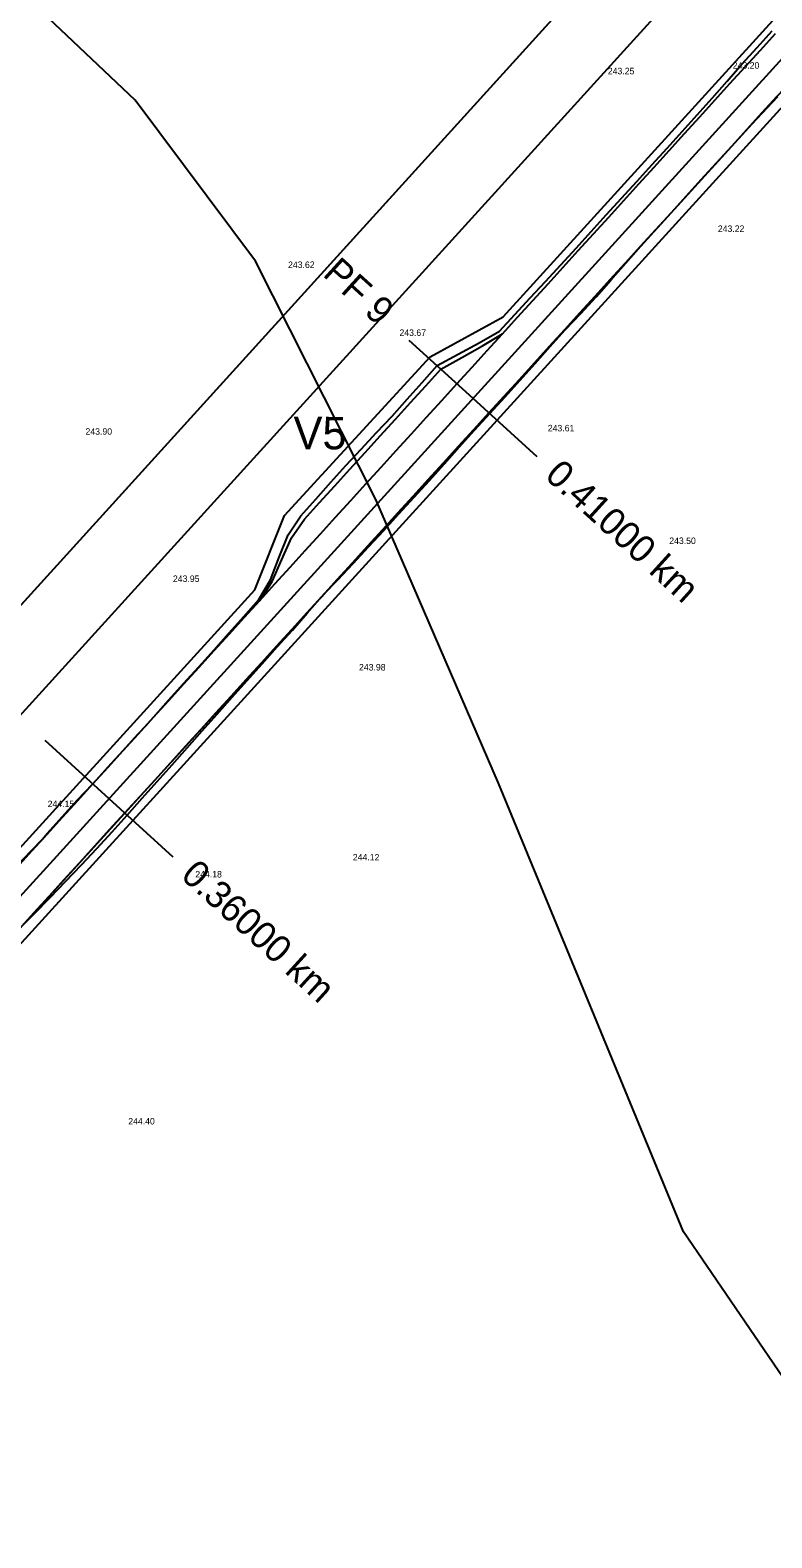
# Model space of a CAD drawing. Extents: x -555887 to -552101, y -1100251 to -1096546.
# Drawn here: x -554649.9 to -554581.4, y -1097394.3 to -1097254.9 of the extents above; entities that cross this region are included whole.
import ezdxf

# ---------------------------------------------------------------- set-up
doc = ezdxf.new("R2010")
doc.units = 0
for name, color, linetype in [('IP_návrh', 7, 'Continuous'), ('PARCELY_cesty', 7, 'Continuous'), ('POLYGONY_POPIS_CESTY', 7, 'Continuous'), ('POLYGONY_SITUACE_PF', 7, 'Continuous'), ('POLYGONY_SITUACE_PF_POPISY', 7, 'Continuous'), ('POLYGONY_SITUACE_PO', 7, 'Continuous'), ('vrstevnice', 7, 'Continuous'), ('Výškopis', 7, 'Continuous'), ('zájem', 7, 'Continuous')]:
    doc.layers.add(name, color=color, linetype=linetype)

msp = doc.modelspace()

# ---------------------------------------------------------------- linework, layer by layer
at = {"layer": 'IP_návrh'}
msp.add_line((-554875.9, -1097565.92), (-554275.99, -1096905.69), dxfattribs=at)
at = {"layer": 'PARCELY_cesty'}
for points in [[(-554879.07, -1097590.15), (-554550.67, -1097229.32), (-554531.76, -1097208.54), (-554275.81, -1096927.3), (-554273.04, -1096923.94), (-554268.63, -1096916.51), (-554265.12, -1096907.97), (-554264.18, -1096901.52)], [(-554875.85, -1097577.71), (-554629.16, -1097306.65), (-554626.42, -1097299.8), (-554612.94, -1097285.13), (-554606.19, -1097281.41), (-554359.61, -1097010.48), (-554356.78, -1097004.21), (-554343, -1096989.28), (-554337.66, -1096986.36), (-554280.34, -1096923.38), (-554277.96, -1096920.48), (-554274.11, -1096913.98), (-554271.59, -1096906.68), (-554270.35, -1096901.41)]]:
    msp.add_lwpolyline(points, dxfattribs=at)
at = {"layer": 'POLYGONY_SITUACE_PF'}
for p, q in [((-554614.91, -1097283.57), (-554609, -1097288.95)), ((-554609, -1097288.95), (-554603.08, -1097294.34)), ((-554648.57, -1097320.55), (-554642.65, -1097325.93)), ((-554642.65, -1097325.93), (-554636.74, -1097331.32))]:
    msp.add_line(p, q, dxfattribs=at)
at = {"layer": 'POLYGONY_SITUACE_PO'}
for p, q in [((-554884.96, -1097592.18), (-554278.08, -1096925.34)), ((-554878.71, -1097588.28), (-554338.29, -1096994.47)), ((-554582.73, -1097256.52), (-554581.33, -1097254.98)), ((-554584.13, -1097258.06), (-554582.73, -1097256.52)), ((-554582.43, -1097256.79), (-554581.03, -1097255.25)), ((-554582.43, -1097256.79), (-554581.03, -1097255.25)), ((-554583.83, -1097258.33), (-554582.43, -1097256.79)), ((-554583.83, -1097258.33), (-554582.43, -1097256.79)), ((-554585.5, -1097259.63), (-554584.13, -1097258.06)), ((-554585.24, -1097259.87), (-554583.83, -1097258.33)), ((-554585.24, -1097259.87), (-554583.83, -1097258.33)), ((-554586.88, -1097261.2), (-554585.5, -1097259.63)), ((-554586.64, -1097261.41), (-554585.24, -1097259.87)), ((-554586.64, -1097261.41), (-554585.24, -1097259.87)), ((-554588.27, -1097262.75), (-554586.88, -1097261.2)), ((-554588.04, -1097262.95), (-554586.64, -1097261.41)), ((-554588.04, -1097262.95), (-554586.64, -1097261.41)), ((-554582.28, -1097262.56), (-554580.88, -1097261.02)), ((-554582.25, -1097262.59), (-554580.82, -1097261.07)), ((-554589.65, -1097264.3), (-554588.27, -1097262.75)), ((-554589.44, -1097264.49), (-554588.04, -1097262.95)), ((-554589.44, -1097264.49), (-554588.04, -1097262.95)), ((-554583.68, -1097264.11), (-554582.28, -1097262.56)), ((-554583.67, -1097264.12), (-554582.25, -1097262.59)), ((-554591.05, -1097265.85), (-554589.65, -1097264.3)), ((-554590.85, -1097266.04), (-554589.44, -1097264.49)), ((-554590.85, -1097266.04), (-554589.44, -1097264.49)), ((-554585.08, -1097265.65), (-554583.68, -1097264.11)), ((-554585.07, -1097265.66), (-554583.67, -1097264.12)), ((-554592.45, -1097267.39), (-554591.05, -1097265.85)), ((-554592.25, -1097267.58), (-554590.85, -1097266.04)), ((-554592.25, -1097267.58), (-554590.85, -1097266.04)), ((-554586.48, -1097267.19), (-554585.08, -1097265.65)), ((-554586.48, -1097267.19), (-554585.07, -1097265.66)), ((-554593.86, -1097268.92), (-554592.45, -1097267.39)), ((-554593.65, -1097269.12), (-554592.25, -1097267.58)), ((-554593.65, -1097269.12), (-554592.25, -1097267.58)), ((-554587.89, -1097268.73), (-554586.48, -1097267.19)), ((-554587.88, -1097268.73), (-554586.48, -1097267.19)), ((-554595.26, -1097270.46), (-554593.86, -1097268.92)), ((-554595.05, -1097270.66), (-554593.65, -1097269.12)), ((-554595.05, -1097270.66), (-554593.65, -1097269.12)), ((-554589.29, -1097270.27), (-554587.89, -1097268.73)), ((-554589.29, -1097270.27), (-554587.88, -1097268.73)), ((-554596.67, -1097272.01), (-554595.26, -1097270.46)), ((-554590.69, -1097271.81), (-554589.29, -1097270.27)), ((-554590.69, -1097271.81), (-554589.29, -1097270.27)), ((-554596.45, -1097272.2), (-554595.05, -1097270.66)), ((-554596.45, -1097272.2), (-554595.05, -1097270.66)), ((-554592.09, -1097273.35), (-554590.69, -1097271.81)), ((-554592.08, -1097273.36), (-554590.69, -1097271.81)), ((-554598.07, -1097273.55), (-554596.67, -1097272.01)), ((-554597.86, -1097273.74), (-554596.45, -1097272.2)), ((-554597.86, -1097273.74), (-554596.45, -1097272.2)), ((-554599.47, -1097275.09), (-554598.07, -1097273.55)), ((-554599.26, -1097275.28), (-554597.86, -1097273.74)), ((-554599.26, -1097275.28), (-554597.86, -1097273.74)), ((-554593.5, -1097274.89), (-554592.09, -1097273.35)), ((-554593.48, -1097274.9), (-554592.08, -1097273.36)), ((-554600.87, -1097276.63), (-554599.47, -1097275.09)), ((-554600.66, -1097276.82), (-554599.26, -1097275.28)), ((-554600.66, -1097276.82), (-554599.26, -1097275.28)), ((-554594.9, -1097276.43), (-554593.5, -1097274.89)), ((-554594.87, -1097276.45), (-554593.48, -1097274.9)), ((-554602.3, -1097278.15), (-554600.87, -1097276.63)), ((-554602.06, -1097278.36), (-554600.66, -1097276.82)), ((-554602.06, -1097278.36), (-554600.66, -1097276.82)), ((-554596.3, -1097277.97), (-554594.9, -1097276.43)), ((-554596.25, -1097278.02), (-554594.87, -1097276.45)), ((-554603.71, -1097279.68), (-554602.3, -1097278.15)), ((-554603.47, -1097279.9), (-554602.06, -1097278.36)), ((-554603.47, -1097279.9), (-554602.06, -1097278.36)), ((-554597.7, -1097279.51), (-554596.3, -1097277.97)), ((-554597.62, -1097279.59), (-554596.25, -1097278.02)), ((-554605.12, -1097281.21), (-554603.71, -1097279.68)), ((-554604.87, -1097281.44), (-554603.47, -1097279.9)), ((-554604.87, -1097281.44), (-554603.47, -1097279.9)), ((-554599.11, -1097281.05), (-554597.7, -1097279.51)), ((-554599.03, -1097281.12), (-554597.62, -1097279.59)), ((-554606.54, -1097282.74), (-554605.12, -1097281.21)), ((-554606.27, -1097282.98), (-554604.87, -1097281.44)), ((-554606.27, -1097282.98), (-554604.87, -1097281.44)), ((-554600.51, -1097282.59), (-554599.11, -1097281.05)), ((-554600.46, -1097282.64), (-554599.03, -1097281.12)), ((-554608.42, -1097283.84), (-554606.54, -1097282.74)), ((-554608.12, -1097284.11), (-554606.27, -1097282.98)), ((-554607.67, -1097284.52), (-554606.27, -1097282.98)), ((-554601.91, -1097284.14), (-554600.51, -1097282.59)), ((-554601.86, -1097284.18), (-554600.46, -1097282.64)), ((-554610.37, -1097284.88), (-554608.42, -1097283.84)), ((-554610.04, -1097285.19), (-554608.12, -1097284.11)), ((-554603.31, -1097285.68), (-554601.91, -1097284.14)), ((-554603.24, -1097285.74), (-554601.86, -1097284.18)), ((-554612.31, -1097285.93), (-554610.37, -1097284.88)), ((-554611.96, -1097286.26), (-554610.04, -1097285.19)), ((-554609.07, -1097286.07), (-554607.67, -1097284.52)), ((-554604.71, -1097287.22), (-554603.31, -1097285.68)), ((-554604.63, -1097287.29), (-554603.24, -1097285.74)), ((-554613.7, -1097287.49), (-554612.31, -1097285.93)), ((-554613.36, -1097287.8), (-554611.96, -1097286.26)), ((-554610.48, -1097287.61), (-554609.07, -1097286.07)), ((-554606.12, -1097288.76), (-554604.71, -1097287.22)), ((-554615.09, -1097289.04), (-554613.7, -1097287.49)), ((-554614.76, -1097289.34), (-554613.36, -1097287.8)), ((-554611.88, -1097289.15), (-554610.48, -1097287.61)), ((-554606.03, -1097288.83), (-554604.63, -1097287.29)), ((-554616.48, -1097290.59), (-554615.09, -1097289.04)), ((-554616.16, -1097290.88), (-554614.76, -1097289.34)), ((-554613.28, -1097290.69), (-554611.88, -1097289.15)), ((-554607.52, -1097290.3), (-554606.12, -1097288.76)), ((-554607.45, -1097290.36), (-554606.03, -1097288.83)), ((-554617.9, -1097292.12), (-554616.48, -1097290.59)), ((-554617.57, -1097292.42), (-554616.16, -1097290.88)), ((-554614.68, -1097292.23), (-554613.28, -1097290.69)), ((-554608.92, -1097291.84), (-554607.52, -1097290.3)), ((-554608.86, -1097291.9), (-554607.45, -1097290.36)), ((-554619.32, -1097293.64), (-554617.9, -1097292.12)), ((-554618.97, -1097293.96), (-554617.57, -1097292.42)), ((-554616.09, -1097293.77), (-554614.68, -1097292.23)), ((-554610.32, -1097293.38), (-554608.92, -1097291.84)), ((-554610.25, -1097293.45), (-554608.86, -1097291.9)), ((-554620.74, -1097295.16), (-554619.32, -1097293.64)), ((-554620.37, -1097295.5), (-554618.97, -1097293.96)), ((-554617.49, -1097295.31), (-554616.09, -1097293.77)), ((-554611.73, -1097294.92), (-554610.32, -1097293.38)), ((-554611.63, -1097295), (-554610.25, -1097293.45)), ((-554622.14, -1097296.71), (-554620.74, -1097295.16)), ((-554621.77, -1097297.05), (-554620.37, -1097295.5)), ((-554618.89, -1097296.85), (-554617.49, -1097295.31)), ((-554613.13, -1097296.46), (-554611.73, -1097294.92)), ((-554613.02, -1097296.56), (-554611.63, -1097295)), ((-554623.52, -1097298.27), (-554622.14, -1097296.71)), ((-554620.29, -1097298.39), (-554618.89, -1097296.85)), ((-554614.53, -1097298), (-554613.13, -1097296.46)), ((-554614.43, -1097298.09), (-554613.02, -1097296.56)), ((-554624.91, -1097299.83), (-554623.52, -1097298.27)), ((-554623.17, -1097298.59), (-554621.77, -1097297.05)), ((-554621.7, -1097299.93), (-554620.29, -1097298.39)), ((-554615.93, -1097299.54), (-554614.53, -1097298)), ((-554615.84, -1097299.63), (-554614.43, -1097298.09)), ((-554624.58, -1097300.13), (-554623.17, -1097298.59)), ((-554617.33, -1097301.08), (-554615.93, -1097299.54)), ((-554617.25, -1097301.16), (-554615.84, -1097299.63)), ((-554626.07, -1097301.58), (-554624.91, -1097299.83)), ((-554625.77, -1097301.85), (-554624.58, -1097300.13)), ((-554623.1, -1097301.47), (-554621.7, -1097299.93)), ((-554618.74, -1097302.62), (-554617.33, -1097301.08)), ((-554618.66, -1097302.69), (-554617.25, -1097301.16)), ((-554626.91, -1097303.64), (-554626.07, -1097301.58)), ((-554626.66, -1097303.86), (-554625.77, -1097301.85)), ((-554624.5, -1097303.01), (-554623.1, -1097301.47)), ((-554627.71, -1097305.72), (-554626.91, -1097303.64)), ((-554627.55, -1097305.87), (-554626.66, -1097303.86)), ((-554625.9, -1097304.55), (-554624.5, -1097303.01)), ((-554620.14, -1097304.17), (-554618.74, -1097302.62)), ((-554620.08, -1097304.22), (-554618.66, -1097302.69)), ((-554627.3, -1097306.1), (-554625.9, -1097304.55)), ((-554621.54, -1097305.71), (-554620.14, -1097304.17)), ((-554621.5, -1097305.74), (-554620.08, -1097304.22)), ((-554628.8, -1097307.55), (-554627.71, -1097305.72)), ((-554628.71, -1097307.64), (-554627.55, -1097305.87)), ((-554628.71, -1097307.64), (-554627.3, -1097306.1)), ((-554622.94, -1097307.25), (-554621.54, -1097305.71)), ((-554622.79, -1097307.07), (-554621.5, -1097305.74)), ((-554630.17, -1097309.12), (-554628.8, -1097307.55)), ((-554630.11, -1097309.18), (-554628.71, -1097307.64)), ((-554630.11, -1097309.18), (-554628.71, -1097307.64)), ((-554624.35, -1097308.79), (-554622.94, -1097307.25)), ((-554624.31, -1097308.82), (-554622.94, -1097307.25)), ((-554622.94, -1097307.25), (-554622.79, -1097307.07)), ((-554631.56, -1097310.67), (-554630.17, -1097309.12)), ((-554631.51, -1097310.72), (-554630.11, -1097309.18)), ((-554631.51, -1097310.72), (-554630.11, -1097309.18)), ((-554625.75, -1097310.33), (-554624.35, -1097308.79)), ((-554625.69, -1097310.38), (-554624.31, -1097308.82)), ((-554632.95, -1097312.22), (-554631.56, -1097310.67)), ((-554632.91, -1097312.26), (-554631.51, -1097310.72)), ((-554632.91, -1097312.26), (-554631.51, -1097310.72)), ((-554627.15, -1097311.87), (-554625.75, -1097310.33)), ((-554627.08, -1097311.93), (-554625.69, -1097310.38)), ((-554634.34, -1097313.77), (-554632.95, -1097312.22)), ((-554634.32, -1097313.8), (-554632.91, -1097312.26)), ((-554634.32, -1097313.8), (-554632.91, -1097312.26)), ((-554628.55, -1097313.41), (-554627.15, -1097311.87)), ((-554628.47, -1097313.48), (-554627.08, -1097311.93)), ((-554629.95, -1097314.95), (-554628.55, -1097313.41)), ((-554629.86, -1097315.04), (-554628.47, -1097313.48)), ((-554635.75, -1097315.31), (-554634.34, -1097313.77)), ((-554635.72, -1097315.34), (-554634.32, -1097313.8)), ((-554635.72, -1097315.34), (-554634.32, -1097313.8)), ((-554631.36, -1097316.49), (-554629.95, -1097314.95)), ((-554631.25, -1097316.59), (-554629.86, -1097315.04)), ((-554637.15, -1097316.85), (-554635.75, -1097315.31)), ((-554637.12, -1097316.88), (-554635.72, -1097315.34)), ((-554637.12, -1097316.88), (-554635.72, -1097315.34)), ((-554632.76, -1097318.03), (-554631.36, -1097316.49)), ((-554638.54, -1097318.41), (-554637.15, -1097316.85)), ((-554638.52, -1097318.42), (-554637.12, -1097316.88)), ((-554638.52, -1097318.42), (-554637.12, -1097316.88)), ((-554632.64, -1097318.14), (-554631.25, -1097316.59)), ((-554639.94, -1097319.95), (-554639.24, -1097319.21)), ((-554639.92, -1097319.96), (-554638.52, -1097318.42)), ((-554639.92, -1097319.96), (-554638.52, -1097318.42)), ((-554639.24, -1097319.21), (-554638.54, -1097318.41)), ((-554634.16, -1097319.57), (-554632.76, -1097318.03)), ((-554634.03, -1097319.69), (-554632.64, -1097318.14)), ((-554641.33, -1097321.5), (-554639.92, -1097319.96)), ((-554641.33, -1097321.5), (-554639.92, -1097319.96)), ((-554641.07, -1097321.22), (-554639.94, -1097319.95)), ((-554635.56, -1097321.11), (-554634.16, -1097319.57)), ((-554635.4, -1097321.26), (-554634.03, -1097319.69)), ((-554642.74, -1097323.03), (-554641.33, -1097321.5)), ((-554642.73, -1097323.04), (-554641.33, -1097321.5)), ((-554642.73, -1097323.04), (-554641.33, -1097321.5)), ((-554641.33, -1097321.5), (-554641.07, -1097321.22)), ((-554636.97, -1097322.65), (-554635.56, -1097321.11)), ((-554636.79, -1097322.82), (-554635.4, -1097321.26)), ((-554644.13, -1097324.58), (-554642.73, -1097323.04)), ((-554644.13, -1097324.58), (-554642.73, -1097323.04)), ((-554643.52, -1097323.91), (-554642.74, -1097323.03)), ((-554638.37, -1097324.2), (-554636.97, -1097322.65)), ((-554638.18, -1097324.37), (-554636.79, -1097322.82)), ((-554645.57, -1097326.09), (-554644.14, -1097324.57)), ((-554645.53, -1097326.13), (-554644.13, -1097324.58)), ((-554645.53, -1097326.13), (-554644.13, -1097324.58)), ((-554644.14, -1097324.57), (-554643.52, -1097323.91)), ((-554639.77, -1097325.74), (-554638.37, -1097324.2)), ((-554639.58, -1097325.91), (-554638.18, -1097324.37)), ((-554646.98, -1097327.62), (-554645.57, -1097326.09)), ((-554646.94, -1097327.67), (-554645.53, -1097326.13)), ((-554646.94, -1097327.67), (-554645.53, -1097326.13)), ((-554641.17, -1097327.28), (-554639.77, -1097325.74)), ((-554640.95, -1097327.48), (-554639.58, -1097325.91)), ((-554648.35, -1097329.19), (-554646.98, -1097327.62)), ((-554648.34, -1097329.21), (-554646.94, -1097327.67)), ((-554648.34, -1097329.21), (-554646.94, -1097327.67)), ((-554642.58, -1097328.82), (-554641.17, -1097327.28)), ((-554642.36, -1097329.01), (-554640.95, -1097327.48)), ((-554643.98, -1097330.36), (-554642.58, -1097328.82)), ((-554643.77, -1097330.55), (-554642.36, -1097329.01)), ((-554649.77, -1097330.72), (-554648.81, -1097329.73)), ((-554649.74, -1097330.75), (-554648.34, -1097329.21)), ((-554649.74, -1097330.75), (-554648.34, -1097329.21)), ((-554648.81, -1097329.73), (-554648.35, -1097329.19)), ((-554645.38, -1097331.9), (-554643.98, -1097330.36)), ((-554651.22, -1097332.22), (-554649.77, -1097330.72)), ((-554651.14, -1097332.29), (-554649.74, -1097330.75)), ((-554651.14, -1097332.29), (-554649.74, -1097330.75)), ((-554645.18, -1097332.08), (-554643.77, -1097330.55)), ((-554646.78, -1097333.44), (-554645.38, -1097331.9)), ((-554646.62, -1097333.58), (-554645.18, -1097332.08)), ((-554648.18, -1097334.98), (-554646.78, -1097333.44)), ((-554648.08, -1097335.08), (-554646.62, -1097333.58)), ((-554649.59, -1097336.52), (-554648.18, -1097334.98)), ((-554649.53, -1097336.57), (-554648.08, -1097335.08)), ((-554650.99, -1097338.06), (-554649.59, -1097336.52)), ((-554650.84, -1097337.9), (-554649.53, -1097336.57))]:
    msp.add_line(p, q, dxfattribs=at)
at = {"layer": 'vrstevnice'}
msp.add_lwpolyline([(-554569.86, -1097394.82), (-554589.52, -1097366), (-554606.63, -1097324.51), (-554617.97, -1097298.3), (-554629.1, -1097276.28), (-554640.23, -1097261.4), (-554661.45, -1097241.3), (-554676.78, -1097227.62), (-554689.09, -1097213.25), (-554696.75, -1097201.89), (-554700.7, -1097193.07), (-554701.86, -1097182.64), (-554701.16, -1097172.67), (-554697.21, -1097165.71), (-554690.02, -1097160.38), (-554679.33, -1097156.44), (-554658.56, -1097153.34), (-554635.45, -1097151.63), (-554616.18, -1097145.96), (-554603.07, -1097143.66), (-554590.89, -1097147.72), (-554577.5, -1097156.63)], dxfattribs=at)
at = {"layer": 'zájem'}
for points in [[(-554333.96, -1096958.92), (-554536.43, -1097182.04), (-554585.15, -1097235.78), (-554588.14, -1097239.01), (-554733.55, -1097399.26)], [(-554733.55, -1097399.26), (-554588.14, -1097239.01), (-554585.15, -1097235.78), (-554536.43, -1097182.04), (-554333.96, -1096958.92)]]:
    msp.add_lwpolyline(points, dxfattribs=at)

# ---------------------------------------------------------------- texts
at = {"layer": 'POLYGONY_POPIS_CESTY'}
msp.add_text('V5', height=3, rotation=359.8934, dxfattribs=at).set_placement((-554625.59, -1097293.66))
at = {"layer": 'POLYGONY_SITUACE_PF_POPISY'}
for s, p in [('PF 9', (-554622.98, -1097277.58)), ('0.41000 km', (-554602.46, -1097296.26)), ('0.36000 km', (-554636.11, -1097333.23))]:
    msp.add_text(s, height=2.5, rotation=317.6947, dxfattribs=at).set_placement(p)
at = {"layer": 'Výškopis'}
for s, p in [('243.20', (-554584.98, -1097258.49)), ('243.25', (-554596.53, -1097259.01)), ('243.22', (-554586.36, -1097273.58)), ('243.62', (-554626.09, -1097276.91)), ('243.67', (-554615.79, -1097283.19)), ('243.61', (-554602.08, -1097292.01)), ('243.90', (-554644.81, -1097292.32)), ('243.50', (-554590.85, -1097302.42)), ('243.95', (-554636.73, -1097305.93)), ('243.98', (-554619.53, -1097314.11)), ('244.15', (-554648.31, -1097326.74)), ('244.12', (-554620.1, -1097331.67)), ('244.18', (-554634.66, -1097333.24)), ('244.40', (-554640.86, -1097356.07))]:
    msp.add_text(s, height=0.6, dxfattribs=at).set_placement(p)

doc.saveas('drawing.dxf')
